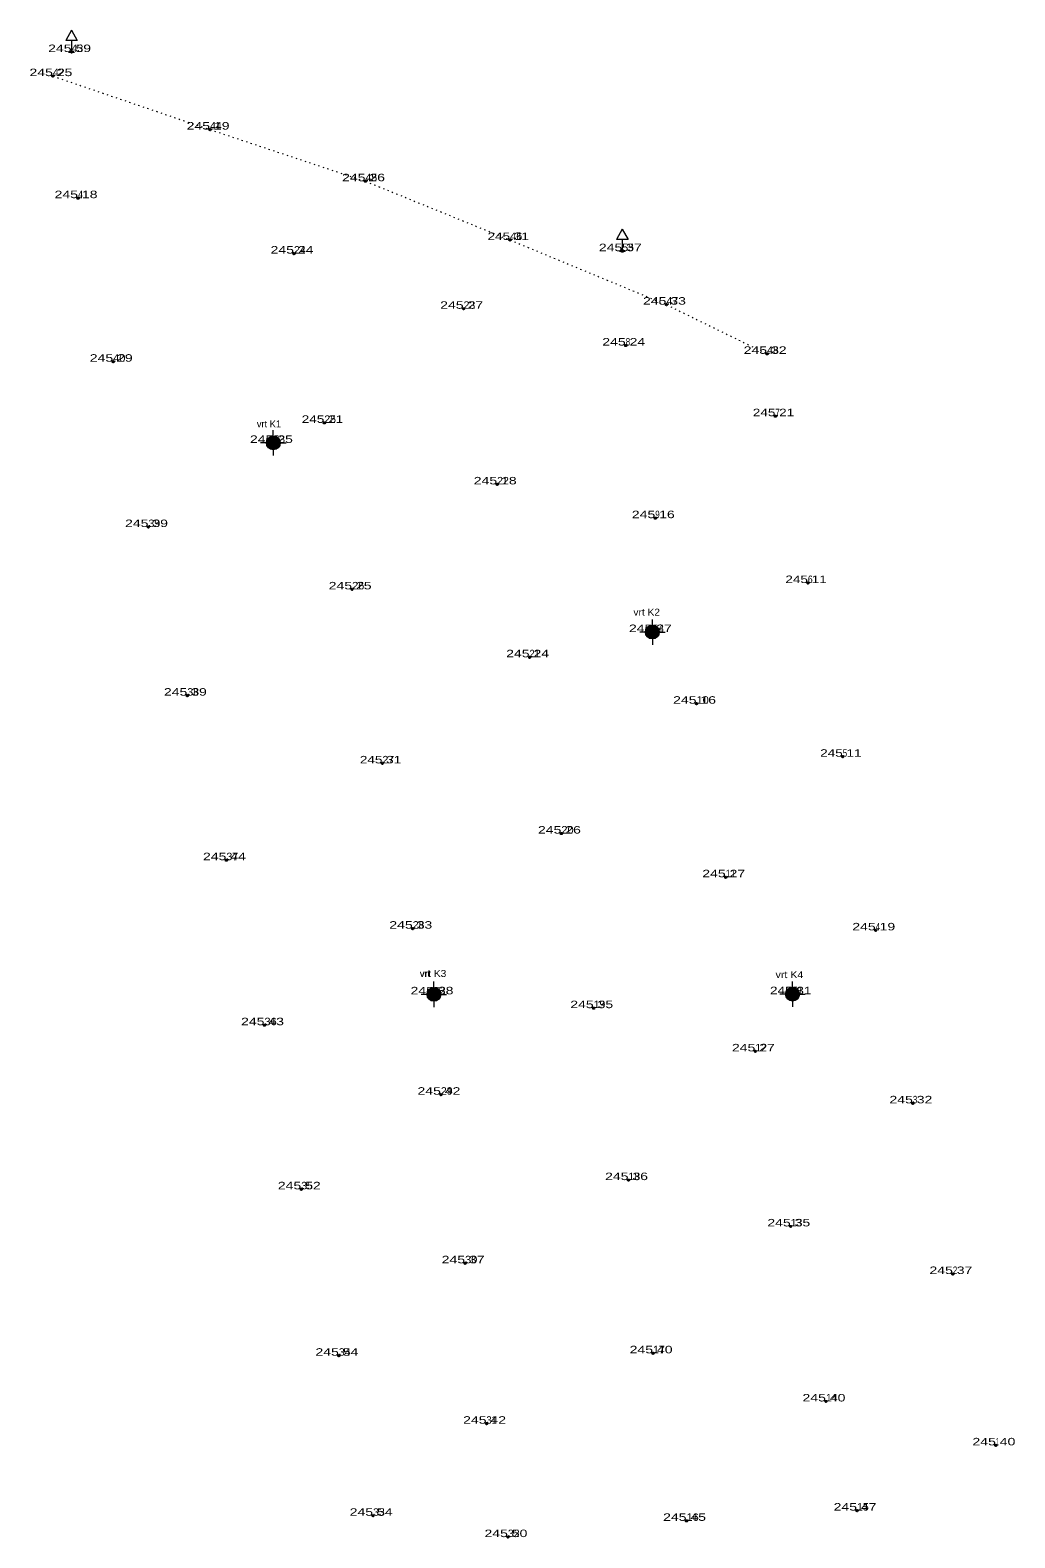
# Model space of a CAD drawing. Extents: x -494684 to -494599, y -1090113 to -1089982.
import ezdxf
from ezdxf.enums import TextEntityAlignment as Align

# ---------------------------------------------------------------- set-up
doc = ezdxf.new("R2010")
doc.units = 0
doc.header["$LTSCALE"] = 0.26
doc.header["$PDMODE"] = 32
doc.header["$PDSIZE"] = 0.13
doc.linetypes.add('DOTTED', pattern=[1.5, 0.3, -1.2])
for name, color, linetype, lineweight in [('23', 7, 'Continuous', 13), ('25', 7, 'Continuous', 13), ('8', 7, 'DOTTED', 13)]:
    doc.layers.add(name, color=color, linetype=linetype, lineweight=lineweight)
for name, color, linetype in [('39', 7, 'Continuous'), ('40', 7, 'Continuous'), ('41', 7, 'Continuous'), ('53', 7, 'Continuous')]:
    doc.layers.add(name, color=color, linetype=linetype)

msp = doc.modelspace()

# ---------------------------------------------------------------- hatches: boundary and pattern name
at = {"layer": '25'}
for points in [[(-494662.42, -1090017.6, 1), (-494663.62, -1090017.6, 1)], [(-494629.55, -1090034.01, 1), (-494630.75, -1090034.01, 1)], [(-494648.49, -1090065.45, 1), (-494649.69, -1090065.45, 1)], [(-494617.39, -1090065.44, 1), (-494618.59, -1090065.44, 1)]]:
    msp.add_hatch(color=256, dxfattribs=at).paths.add_polyline_path(points)

# ---------------------------------------------------------------- linework, layer by layer
at = {"layer": '23'}
for p, q in [((-494680.52, -1089981.78), (-494681.02, -1089982.68)), ((-494680.77, -1089983.68), (-494680.27, -1089983.68)), ((-494680.52, -1089982.68), (-494680.52, -1089983.68)), ((-494632.76, -1089999.06), (-494633.26, -1089999.96)), ((-494632.76, -1089999.96), (-494632.76, -1090000.96)), ((-494633.01, -1090000.96), (-494632.51, -1090000.96))]:
    msp.add_line(p, q, dxfattribs=at)
for points in [[(-494680.52, -1089981.78), (-494680.02, -1089982.68), (-494681.02, -1089982.68)], [(-494632.76, -1089999.06), (-494632.26, -1089999.96), (-494633.26, -1089999.96)]]:
    msp.add_lwpolyline(points, dxfattribs=at)
at = {"layer": '25'}
for p, q in [((-494663.62, -1090017.6), (-494664.12, -1090017.6)), ((-494663.02, -1090017), (-494663.02, -1090016.5)), ((-494662.42, -1090017.6), (-494661.92, -1090017.6)), ((-494663.02, -1090018.2), (-494663.02, -1090018.7)), ((-494630.15, -1090033.41), (-494630.15, -1090032.91)), ((-494630.75, -1090034.01), (-494631.25, -1090034.01)), ((-494630.15, -1090034.61), (-494630.15, -1090035.11)), ((-494629.55, -1090034.01), (-494629.05, -1090034.01)), ((-494649.09, -1090064.85), (-494649.09, -1090064.35)), ((-494617.99, -1090064.84), (-494617.99, -1090064.34)), ((-494649.69, -1090065.45), (-494650.19, -1090065.45)), ((-494649.09, -1090066.05), (-494649.09, -1090066.55)), ((-494648.49, -1090065.45), (-494647.99, -1090065.45)), ((-494618.59, -1090065.44), (-494619.09, -1090065.44)), ((-494617.99, -1090066.04), (-494617.99, -1090066.54)), ((-494617.39, -1090065.44), (-494616.89, -1090065.44))]:
    msp.add_line(p, q, dxfattribs=at)
for centre in [(-494663.02, -1090017.6), (-494630.15, -1090034.01), (-494649.09, -1090065.45), (-494617.99, -1090065.44)]:
    msp.add_circle(centre, 0.6, dxfattribs=at)
at = {"layer": '53'}
for p in [(-494680.52, -1089983.68), (-494682.14, -1089985.77), (-494668.51, -1089990.41), (-494655.03, -1089994.89), (-494679.96, -1089996.36), (-494642.49, -1089999.99), (-494661.23, -1090001.17), (-494632.76, -1090000.96), (-494646.52, -1090005.96), (-494628.93, -1090005.6), (-494632.46, -1090009.15), (-494620.2, -1090009.87), (-494676.91, -1090010.55), (-494658.6, -1090015.86), (-494619.48, -1090015.28), (-494663.02, -1090017.6), (-494643.61, -1090021.2), (-494629.9, -1090024.13), (-494673.85, -1090024.9), (-494656.19, -1090030.31), (-494616.66, -1090029.76), (-494630.15, -1090034.01), (-494640.8, -1090036.2), (-494670.48, -1090039.53), (-494626.32, -1090040.23), (-494613.64, -1090044.83), (-494653.56, -1090045.41), (-494638.04, -1090051.5), (-494667.09, -1090053.81), (-494623.79, -1090055.29), (-494650.93, -1090059.75), (-494610.78, -1090059.9), (-494649.09, -1090065.45), (-494617.99, -1090065.44), (-494635.24, -1090066.65), (-494663.79, -1090068.13), (-494621.22, -1090070.4), (-494648.49, -1090074.16), (-494607.56, -1090074.91), (-494632.22, -1090081.57), (-494660.6, -1090082.37), (-494618.15, -1090085.59), (-494646.39, -1090088.79), (-494604.09, -1090089.72), (-494657.34, -1090096.81), (-494630.09, -1090096.6), (-494615.1, -1090100.78), (-494644.53, -1090102.71), (-494600.36, -1090104.59), (-494654.37, -1090110.7), (-494612.4, -1090110.25), (-494627.19, -1090111.14), (-494642.68, -1090112.55)]:
    msp.add_point(p, dxfattribs=at)
at = {"layer": '8'}
msp.add_lwpolyline([(-494682.14, -1089985.77), (-494668.51, -1089990.41), (-494655.03, -1089994.89), (-494642.49, -1089999.99), (-494628.93, -1090005.6), (-494620.2, -1090009.87)], dxfattribs=at)

# ---------------------------------------------------------------- texts
at = {"layer": '39'}
for s, width, p in [('245.59 ', 1.4, (-494680.52, -1089983.68)), ('245.25 ', 1.4, (-494682.139, -1089985.77)), ('245.19 ', 1.4, (-494668.51, -1089990.41)), ('245.26 ', 1.4, (-494655.03, -1089994.89)), ('245.18 ', 1.4, (-494679.96, -1089996.36)), ('245.31 ', 1.35, (-494642.489, -1089999.99)), ('245.24 ', 1.4, (-494661.23, -1090001.17)), ('245.37 ', 1.4, (-494632.76, -1090000.96)), ('245.27 ', 1.4, (-494646.52, -1090005.96)), ('245.33 ', 1.4, (-494628.93, -1090005.6)), ('245.24 ', 1.4, (-494632.46, -1090009.15)), ('245.29 ', 1.4, (-494676.91, -1090010.55)), ('245.32 ', 1.4, (-494620.2, -1090009.87)), ('245.21 ', 1.35, (-494619.479, -1090015.28)), ('245.21 ', 1.35, (-494658.599, -1090015.86)), ('245.25 ', 1.4, (-494663.019, -1090017.6)), ('245.18 ', 1.4, (-494643.61, -1090021.2)), ('245.39 ', 1.4, (-494673.85, -1090024.9)), ('245.16 ', 1.4, (-494629.9, -1090024.13)), ('245.11 ', 1.35, (-494616.659, -1090029.76)), ('245.25 ', 1.4, (-494656.189, -1090030.31)), ('245.27 ', 1.4, (-494630.15, -1090034.01)), ('245.24 ', 1.4, (-494640.8, -1090036.2)), ('245.39 ', 1.4, (-494670.48, -1090039.53)), ('245.16 ', 1.4, (-494626.32, -1090040.23)), ('245.31 ', 1.35, (-494653.559, -1090045.41)), ('245.11 ', 1.35, (-494613.639, -1090044.83)), ('245.26 ', 1.4, (-494638.04, -1090051.5)), ('245.44 ', 1.4, (-494667.09, -1090053.81)), ('245.27 ', 1.4, (-494623.79, -1090055.29)), ('245.33 ', 1.4, (-494650.93, -1090059.75)), ('245.19 ', 1.4, (-494610.78, -1090059.9)), ('245.38 ', 1.4, (-494649.09, -1090065.45)), ('245.31 ', 1.35, (-494617.989, -1090065.44)), ('245.35 ', 1.4, (-494635.239, -1090066.65)), ('245.43 ', 1.4, (-494663.79, -1090068.13)), ('245.27 ', 1.4, (-494621.22, -1090070.4)), ('245.42 ', 1.4, (-494648.49, -1090074.16)), ('245.32 ', 1.4, (-494607.56, -1090074.91)), ('245.52 ', 1.4, (-494660.6, -1090082.37)), ('245.36 ', 1.4, (-494632.22, -1090081.57)), ('245.35 ', 1.4, (-494618.149, -1090085.59)), ('245.37 ', 1.4, (-494646.39, -1090088.79)), ('245.37 ', 1.4, (-494604.09, -1090089.72)), ('245.54 ', 1.4, (-494657.34, -1090096.81)), ('245.40 ', 1.4, (-494630.089, -1090096.6)), ('245.40 ', 1.4, (-494615.099, -1090100.78)), ('245.42 ', 1.4, (-494644.53, -1090102.71)), ('245.40 ', 1.4, (-494600.359, -1090104.59)), ('245.54 ', 1.4, (-494654.37, -1090110.7)), ('245.45 ', 1.4, (-494627.189, -1090111.14)), ('245.47 ', 1.4, (-494612.4, -1090110.25)), ('245.50 ', 1.4, (-494642.679, -1090112.55))]:
    msp.add_text(s, height=0.65, dxfattribs=dict(at, width=width)).set_placement(p, align=Align.CENTER)
at = {"layer": '40'}
for s, p in [('vrt K1', (-494664.447, -1090016.252)), ('vrt K1', (-494664.447, -1090016.252)), ('vrt', (-494650.324, -1090063.938))]:
    msp.add_text(s, height=0.6, dxfattribs=at).set_placement(p)
for s, width, p in [('vrt K2', 1.1, (-494631.793, -1090032.583)), ('vrt K3', 1.1, (-494650.324, -1090063.938)), ('vrt K4', 1.15, (-494619.466, -1090064.042))]:
    msp.add_text(s, height=0.6, dxfattribs=dict(at, width=width)).set_placement(p)
at = {"layer": '41'}
for s, width, p in [('43', 1.05, (-494680.52, -1089983.68)), ('42', 1.05, (-494682.14, -1089985.77)), ('44', 1.05, (-494668.51, -1089990.41)), ('45', 1.05, (-494655.03, -1089994.89)), ('41', 0.9, (-494679.96, -1089996.36)), ('46', 1.1, (-494642.49, -1089999.99)), ('24', 1.05, (-494661.23, -1090001.17)), ('55', 1.05, (-494632.76, -1090000.96)), ('23', 1.05, (-494646.52, -1090005.96)), ('47', 1.05, (-494628.93, -1090005.6)), ('8', 0.8, (-494632.46, -1090009.15)), ('40', 1.1, (-494676.91, -1090010.55)), ('48', 1.05, (-494620.2, -1090009.87)), ('7', 0.8, (-494619.48, -1090015.28)), ('25', 1.05, (-494658.6, -1090015.86)), ('53', 1.05, (-494663.02, -1090017.6)), ('22', 1.05, (-494643.61, -1090021.2)), ('39', 1.05, (-494673.85, -1090024.9)), ('9', 0.8, (-494629.9, -1090024.13)), ('6', 0.85, (-494616.66, -1090029.76)), ('26', 1.1, (-494656.19, -1090030.31)), ('54', 1.05, (-494630.15, -1090034.01)), ('21', 0.9, (-494640.8, -1090036.2)), ('38', 1.05, (-494670.48, -1090039.53)), ('10', 1.1, (-494626.32, -1090040.23)), ('27', 1.05, (-494653.56, -1090045.41)), ('5', 0.8, (-494613.64, -1090044.83)), ('20', 1.1, (-494638.04, -1090051.5)), ('37', 1.05, (-494667.09, -1090053.81)), ('11', 0.9, (-494623.79, -1090055.29)), ('28', 1.05, (-494650.93, -1090059.75)), ('4', 0.8, (-494610.78, -1090059.9)), ('52', 1.05, (-494649.09, -1090065.45)), ('51', 0.9, (-494617.99, -1090065.44)), ('19', 1.05, (-494635.24, -1090066.65)), ('36', 1.1, (-494663.79, -1090068.13)), ('12', 1.05, (-494621.22, -1090070.4)), ('29', 1.05, (-494648.49, -1090074.16)), ('3', 0.8, (-494607.56, -1090074.91)), ('35', 1.05, (-494660.6, -1090082.37)), ('18', 1.05, (-494632.22, -1090081.57)), ('13', 1.05, (-494618.15, -1090085.59)), ('30', 1.1, (-494646.39, -1090088.79)), ('2', 0.8, (-494604.09, -1090089.72)), ('34', 1.05, (-494657.34, -1090096.81)), ('17', 1.05, (-494630.09, -1090096.6)), ('14', 1.05, (-494615.1, -1090100.78)), ('31', 0.9, (-494644.53, -1090102.71)), ('1', 0.45, (-494600.36, -1090104.59)), ('33', 1.05, (-494654.37, -1090110.7)), ('16', 1.1, (-494627.19, -1090111.14)), ('15', 1.05, (-494612.4, -1090110.25)), ('32', 1.05, (-494642.68, -1090112.55))]:
    msp.add_text(s, height=0.65, dxfattribs=dict(at, width=width)).set_placement(p)

doc.saveas('drawing.dxf')
